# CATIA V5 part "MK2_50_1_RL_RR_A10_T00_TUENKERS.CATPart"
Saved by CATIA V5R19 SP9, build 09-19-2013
Part number: MK2_50_1_RL_RR_A10_T00_TUENKERS
Material "MISCHDICHTE": density 4834.5 kg/m3, Young's modulus 2e+11 Pa, Poisson ratio 0.266
Bounding box of the stored display mesh (mm): x -173.5 to 150.266, y -96.5 to 43, z -119.161 to 119.161
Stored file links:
  G:\Konstruktion\Modelle\Catia_V5\MK2_50_1_RL_RR_A10_T00_TUENKERS.CATPart
  G:\Konstruktion\Modelle\Catia_V5\Spannarme\SPANNARM_KPL_50_A10_216884_TUENKERS.CATPart
  C:\Catia\Tuenkers_B19SP9HF86_64\win_b64\reffiles\standard\MetricThickPitch.txt
  G:\Konstruktion\Modelle\Catia_V5\MK2_50_1_A40_T00_TUENKERS.CATPart
  G:\Konstruktion\Modelle\Catia_V5\V2_50_1_BR3_ZL_ZR_RL_RR_A40_T12_TUENKERS.CATPart
  HANDHEBEL_KPL_50_63_TUENKERS.CATPart
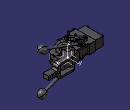
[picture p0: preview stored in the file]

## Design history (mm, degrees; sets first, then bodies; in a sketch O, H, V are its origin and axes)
AxisSystem1: origin (0, 0, 0), X (1, 0, 0), Y (0, 1, 0), Z (0, 0, 1)
Body1 (main body)
  Body2 "*DIT1\\*DIT8\\PartBody ( *SOL6 - wsp HANDHEBEL -  )"
    Solid1 "Solid.1": solid without history
  Assemble1: tool Body2
  Body3 "*DIT1\\*DIT9\\Body.9 ( *SOL4 - wsp T 12 ABFRAGE -  )"
    Sketch1 on face of Solid6, origin (0, 0, 88.5), H (1, 0, 0), V (0, 1, 0)
      line L1 (-98, 23.5) -> (-93.5, 23.5)
      line L2 (-93.5, 23.5) -> (-93.5, -23.5)
      line L3 (-93.5, -23.5) -> (-98, -23.5)
      line L4 (-98, -23.5) -> (-98, 23.5)
      line L5 (-126.5, 11.5) -> (-116.2, 11.5)
      line L6 (-116.2, 11.5) -> (-116.2, -5.5)
      line L7 (-116.2, -5.5) -> (-126.5, -5.5)
      line L8 (-126.5, -5.5) -> (-126.5, 11.5)
      reference projected line E1 (-126.5, -23.5) -> (-93.5, -23.5) from edge [face of Solid6 | face of Solid6]
      reference projected line E2 (-126.5, 23.5) -> (-93.5, 23.5) from edge [face of Solid6 | face of Solid6]
      reference projected line E3 (-93.5, 23.5) -> (-93.5, -23.5) from edge [face of Solid6 | face of Solid6]
      reference projected line E4 (-126.5, 23.5) -> (-93.5, 23.5) from edge [face of Solid6 | face of Solid6]
      reference projected line E5 (-126.5, 23.5) -> (-126.5, -23.5) from edge [face of Solid6 | face of Solid6]
      distance E1 L3 = 0
      distance L1 E2 = 0
      distance L2 L4 = 4.5
      distance L2 E3 = 0
      length L8 = 17
      distance L5 E4 = 12
      distance L6 L4 = 18.2
      distance L8 E5 = 0
      horizontal: L1 H, L3 H, L5 H, L7 H
      vertical: L2 V, L4 V, L6 V, L8 V
    Pad1: profile Sketch1, direction (0, 0, 1), length 8
    Chamfer1: length 4, angle 30, on edge [face of Pad1 from Sketch1.L2 | end face of Pad1]
    Chamfer2: length 8, angle 45, on edge [face of Pad1 from Sketch1.L8 | end face of Pad1]
  Assemble2: tool Body3
  Body4 "*DIT1\\*DIT10\\*DIT17\\PartBody ( *SOL17 - wsp DREHBOLZEN -  )"
    Solid2 "Solid.1": solid without history
  Assemble3: tool Body4
  Body5 "*DIT1\\*DIT10\\*DIT18\\PartBody ( *SOL18 - wsp STOESSEL -  )"
    Solid3 "Solid.1": solid without history
  Assemble4: tool Body5
  Body6 "*DIT1\\*DIT10\\MK_MK2_50_1_A10_A11_A12_T12_081112_3D_xSET3_1.1\\PartBody ( *SOL13 - wsp GEHAEUSE -  )"
    Solid4 "Solid.1": solid without history
  Assemble5: tool Body6
  Body7 "*DIT1\\MK_MK2_50_1_A10_A11_A12_T12_081112_3D_xSET2.1\\PartBody ( *SOL1 - wsp MK_MK2 50_1 -  -Non Smart-  )"
    Solid5 "Solid.1": solid without history
  Assemble6: tool Body7
  Body8 "*DIT1\\MK_MK2_50_1_A10_A11_A12_T12_081112_3D_xSET2.1\\Body.2 ( *SOL2 - wsp MK_MK2 50_1 -  -Non Smart-  )"
    Solid6 "Solid.1": solid without history
  Assemble7: tool Body8
  Body9 "*DIT1\\MK_MK2_50_1_A10_A11_A12_T12_081112_3D_xSET2.1\\Body.3 ( *SOL24 - wsp MK_MK2 50_1 -  )"
    Solid7 "Solid.1": solid without history
  Assemble8: tool Body9
  Body10 "*DIT1\\MK_MK2_50_1_A10_A11_A12_T12_081112_3D_xSET2.1\\Body.4 ( *SOL25 - wsp MK_MK2 50_1 -  )"
    Solid8 "Solid.1": solid without history
  Assemble9: tool Body10
  Body11 "*DIT1\\MK_MK2_50_1_A10_A11_A12_T12_081112_3D_xSET2.1\\Body.5 ( *SOL26 - wsp MK_MK2 50_1 -  )"
    Solid9 "Solid.1": solid without history
  Assemble10: tool Body11
  Body12 "*DIT1\\MK_MK2_50_1_A10_A11_A12_T12_081112_3D_xSET2.1\\Body.6 ( *SOL27 - wsp MK_MK2 50_1 -  )"
    Solid10 "Solid.1": solid without history
  Assemble11: tool Body12
  Body13 "*DIT1\\MK_MK2_50_1_A10_A11_A12_T12_081112_3D_xSET2.1\\Body.7 ( *SOL28 - wsp MK_MK2 50_1 -  )"
    Solid11 "Solid.1": solid without history
  Assemble12: tool Body13
  Rotate1: Axis edge [XY plane of AxisSystem1 | ZX plane of AxisSystem1], Angle 90, ToTransfor Assemble12
Body14 "Spannarm_kpl_50_A10_216884_Tuenkers", material "Steel"
  Sketch2 on xy-plane, origin (0, 0, 0), H (1, 0, 0), V (0, 1, 0)
    line L1 (43, 144) -> (15, 144)
    line L2 (35.6421, 1.701) -> (16.9706, -16.9706)
    line L3 (9.5, 9.5) -> (9.5, -9.5)
    line L4 (9.5, 9.5) -> (-9.5, 9.5)
    line L5 (-16.9706, 16.9706) -> (-9.5, 9.5)
    line L6 (10.6421, 44.5833) -> (-16.9706, 16.9706)
    line L7 (16.5, 58.7254) -> (16.5, 78.5)
    line L8 (43, 144) -> (43, 80)
    line L9 (9.5, -9.5) -> (16.9706, -16.9706)
    point P8 (43, 9.0589)
    point P9 (16.5, 51.7188)
    reference intersected line E1 through (0, 0) direction (-1, 0)
    reference intersected line E2 through (0, 0) direction (0, 1)
    reference intersected line E3 through (0, 0) direction (-0.7071, -0.7071)
    line L10 (41.5, 78.5) -> (41.5, 15.8431)
    reference intersected line E4 through (0, 0) direction (0, 1) from yz-plane
    line L11 (15, 80) -> (15, 144)
    point P10 (15, 80)
    reference intersected line E5 through (0, 0) direction (0, 1) from yz-plane
    arc A1 centre (43, 78.5) radius 1.5 from (41.5, 78.5) to (43, 80) cw
    arc A2 centre (15, 78.5) radius 1.5 from (16.5, 78.5) to (15, 80) ccw
    arc A3 centre (21.5, 15.8431) radius 20 from (35.6421, 1.701) to (41.5, 15.8431) ccw
    arc A4 centre (-3.5, 58.7254) radius 20 from (10.6421, 44.5833) to (16.5, 58.7254) ccw
    length L3 = 19
    length L4 = 19
    angle L5 L4 = 45
    angle L3 L9 = 45
    distance L2 L6 = 48
    distance L4 L1 = 134.5
    distance P9 L4 = 42.2188
    distance L4 E1 = 9.5
    distance L3 E2 = 9.5
    distance L2 E3 = 24
    distance L10 E4 = 41.5
    distance E5 L11 = 15
    distance L7 L10 = 25
    distance L8 L11 = 28
    length L8 = 64
    radius A3 = 20
    radius A4 = 20
    radius A1 = 1.5
    radius A2 = 1.5
    length L11 = 64
    vertical: L3 V
    horizontal: L4 H
    tangency: A3 L10, L2 A3, L7 A2, L10 A1, L7 A4, L6 A4
  Pad2: profile Sketch2, direction (0, 0, 1), length 34, mirrored extent
  Chamfer3: length 0.1, angle 45, on edge [start face of Pad2 | face of Pad2 from Sketch2.L3]; edge [start face of Pad2 | face of Pad2 from Sketch2.L4]; edge [face of Pad2 from Sketch2.L4 | end face of Pad2]; edge [face of Pad2 from Sketch2.L3 | end face of Pad2]
  Sketch3 on face of Pad2 from Sketch2.L8, origin (43, 0, 0), H (0, 1, 0), V (0, 0, 1)
    line L1 (144, -10) -> (144, 10)
    line L2 (103, 10) -> (144, 10)
    arc A1 centre (103, 18) radius 8 from (103, 10) to (95, 18) cw
    line L3 (95, 18) -> (95, 21.0383)
    line L4 (-18, 34) -> (75, 34)
    line L5 (-18, 34) -> (-18, 25)
    line L6 (74, 25) -> (-18, 25)
    arc A2 centre (74, 19) radius 6 from (74, 25) to (80, 19) cw
    line L7 (80, 19) -> (80, -19)
    arc A3 centre (74, -19) radius 6 from (80, -19) to (74, -25) cw
    line L8 (-18, -25) -> (74, -25)
    line L9 (-18, -25) -> (-18, -34)
    line L10 (75, -34) -> (-18, -34)
    line L11 (95, -21.0383) -> (95, -18)
    arc A4 centre (103, -18) radius 8 from (95, -18) to (103, -10) cw
    line L12 (103, -10) -> (144, -10)
    reference intersected line E1 through (0, 0) direction (-1, 0) from xy-plane
    reference intersected line E2 through (0, 0) direction (0, 1) from zx-plane
    reference intersected line E3 through (0, 0) direction (0, 1) from zx-plane
    reference intersected line E4 through (0, 0) direction (0, 1) from zx-plane
    line L13 (-23, -39) -> (149, -39)
    line L14 (149, -39) -> (149, 39)
    line L15 (149, 39) -> (-23, 39)
    line L16 (-23, 39) -> (-23, -39)
    reference intersected line E5 through (0, 0) direction (-1, 0) from xy-plane
    reference intersected line E6 through (0, 0) direction (0, 1) from zx-plane
    line L17 (75.5176, -33.9319) -> (87.5882, -30.6976)
    point P18 (95, -24)
    arc A5 centre (85, -21.0383) radius 10 from (95, -21.0383) to (87.5882, -30.6976) cw
    arc A6 centre (75, -32) radius 2 from (75, -34) to (75.5176, -33.9319) ccw
    point P23 (75, -34)
    line L18 (87.5882, 30.6976) -> (75.5176, 33.9319)
    arc A7 centre (75, 32) radius 2 from (75, 34) to (75.5176, 33.9319) cw
    point P26 (75, 34)
    arc A8 centre (85, 21.0383) radius 10 from (87.5882, 30.6976) to (95, 21.0383) cw
    distance L12 E1 = 10
    distance L12 L2 = 20
    distance L4 L10 = 68
    distance L6 L8 = 50
    distance L10 L12 = 24
    distance L8 L10 = 9
    radius A2 = 6
    radius A3 = 6
    radius A1 = 8
    radius A4 = 8
    distance L7 E2 = 80
    distance L3 E3 = 95
    distance L1 L5 = 162
    distance E4 L1 = 144
    distance L16 L14 = 172
    distance L15 L13 = 78
    distance L13 E5 = 39
    distance L14 E6 = 149
    radius A5 = 10
    angle L10 L17 = 15
    radius A6 = 2
    distance L11 P23 = 20
    angle L4 L18 = 15
    distance P26 L3 = 20
    radius A8 = 10
    radius A7 = 2
    tangency: L6 A2, A2 L7, L7 A3, A3 L8, L3 A1, A1 L2, A4 L12, A4 L11, A5 L11, A5 L17, A6 L10, A6 L17, A7 L4, A7 L18, A8 L18, A8 L3
    vertical: L1 V, L14 V, L16 V
    horizontal: L12 H, L13 H, L15 H
    coincidence: L5 L9, L11 L3, L11 P18
  Pocket1: profile Sketch3, direction (-1, 0, 0), length 91
  Sketch4 on face of Pad2 from Sketch2.L8, origin (43, 131.0889, -0.3784), H (0, 1, 0), V (0, 0, 1)
    point P1 (3.9111, 0.3784)
    reference intersected line E1 through (0, 0.3784) direction (-1, 0) from xy-plane
    reference intersected line E2 through (-131.0889, 0) direction (0, 1) from zx-plane
    distance P1 E2 = 135
    coincidence: P1 E1
  Hole1: placed by Sketch4, at (43, 135, 0) direction (-1, 0, 0), diameter 6, through (limit type 6)
  Sketch5 on face of Pad2 from Sketch2.L8, origin (43, 113.9529, 0.5693), H (0, 1, 0), V (0, 0, 1)
    point P1 (-8.9529, -0.5693)
    reference projected point E1 (21.0471, -0.5693) from axis of face of Hole1
    reference intersected line E2 through (0, -0.5693) direction (-1, 0) from xy-plane
    distance P1 E1 = 30
    coincidence: P1 E2
  Hole2: placed by Sketch5, at (43, 105, 0) direction (-1, 0, 0), diameter 6, through (limit type 6)
  Sketch6 on face of Pad2 from Sketch2.L8, origin (43, 123.4122, -0.1089), H (0, 1, 0), V (0, 0, 1)
    point P1 (-3.4122, 0.1089)
    reference projected point E1 (11.5878, 0.1089) from axis of face of Hole1
    reference projected point E2 (-18.4122, 0.1089) from axis of face of Hole2
    distance P1 E1 = 15
    distance E2 P1 = 15
  Hole3: placed by Sketch6, at (43, 120, 0) direction (-1, 0, 0), diameter 9, through (limit type 6)
  Sketch7 on face of Pad2 from Sketch2.L8, origin (43, 93.5248, 1.4062), H (0, 1, 0), V (0, 0, 1)
    point P1 (-3.5248, -1.4062)
    reference projected point E1 (26.4752, -1.4062) from axis of face of Hole3
    reference projected point E2 (11.4752, -1.4062) from axis of face of Hole2
    distance P1 E1 = 30
    distance P1 E2 = 15
  Hole4: placed by Sketch7, at (43, 90, 0) direction (-1, 0, 0), diameter 9, through (limit type 6)
  Sketch8 on face of Pad2 from Sketch2.L9, origin (13.7879, -13.7879, 28.7565), H (0.7071, -0.7071, 0), V (0, 0, 1)
    point P1 (-1.4991, 0.2435)
    reference intersected line E1 through (0, -28.7565) direction (-1, 0) from xy-plane
    reference projected line E2 (-19.4991, -62.7565) -> (-19.4991, 5.2435) from edge [face of Pad2 from Sketch2.L3 | face of Pad2 from Sketch2.L4]
    distance P1 E1 = 29
    distance E2 P1 = 18
  Hole5: placed by Sketch8, at (12.7279, -12.7279, 29) direction (0.7071, 0.7071, 0), diameter 4.917, depth 16, V-bottom angle 120, threaded "M6", thread diameter 6, thread depth 14, pitch 1
  RectPattern1: of Hole5, direction 1 instances 2, spacing 58, along edge [face of Pad2 from Sketch2.L3 | face of Pad2 from Sketch2.L4] reversed, direction 2 instances 2, spacing 36, along edge [face of Pad2 from Sketch2.L9 | face of Pocket1] reversed
  Body15 "KLEMMFLANSCH KPL"
    Sketch9 on xy-plane, origin (0, 0, 0), H (1, 0, 0), V (0, 1, 0)
      line L1 (-18.3848, 15.5563) -> (-26.8771, 7.064)
      line L2 (-26.8771, 7.064) -> (-18.7454, -1.0677)
      line L3 (-18.7454, -1.0677) -> (-23.6951, -6.0175)
      line L4 (-23.6951, -6.0175) -> (-6.0175, -23.6951)
      line L5 (-6.0175, -23.6951) -> (-1.0677, -18.7454)
      line L6 (-1.0677, -18.7454) -> (7.064, -26.8771)
      line L7 (7.064, -26.8771) -> (16.9635, -16.9776)
      line L8 (16.9635, -16.9776) -> (9.3267, -9.3409)
      line L9 (9.3267, -9.3409) -> (-9.3409, -9.3409)
      point P10 (-9.3409, -9.3409)
      line L10 (-9.3409, -9.3409) -> (-9.3409, 6.5125)
      line L11 (-9.3409, 6.5125) -> (-18.3848, 15.5563)
      reference intersected line E1 through (0, 0) direction (-0.7071, -0.7071)
      reference intersected line E2 through (0, 0) direction (-0.7071, 0.7071)
      distance L4 L8 = 21
      angle L5 L6 = 90
      angle L9 L8 = 45
      distance L7 L5 = 11.5
      distance L5 L3 = 25
      distance L7 L1 = 48
      distance P10 L8 = 13.2
      distance P10 L5 = 12.5
      distance L4 L6 = 7
      angle L9 L10 = 90
      distance E2 L11 = 2
      distance L11 L8 = 1.99
      coincidence: L2 L6, E1 P10
    Pad3: profile Sketch9, direction (0, 0, 1), length 34, opposite side length -24
    Sketch10 on face of Pad3 from Sketch9.L6, origin (-9.9066, -9.9066, 0), H (0.7071, -0.7071, 0), V (0, 0, 1)
      circle A1 centre (18, 29) radius 5
      point P1 (18, 29)
      point P2 (18, 29)
      reference projected line E1 (12.5, 34) -> (24, 34) from edge [face of Pad3 from Sketch9.L6 | end face of Pad3]
      reference projected line E2 (24, 24) -> (24, 34) from edge [face of Pad3 from Sketch9.L7 | face of Pad3 from Sketch9.L6]
      radius A1 = 5
      distance E1 P2 = 5
      distance P2 E2 = 6
      coincidence: P2 P1
    Pad4: profile Sketch10, direction (-0.7071, -0.7071, 0), length 1.2
    RectPattern2: of Pad4, direction 1 instances 2, spacing 36, along edge [start face of Pad3 | face of Pad3 from Sketch9.L4] reversed
    Chamfer4: length 0.1, angle 45, on edge [face of Pad4 from Sketch10.A1 | end face of Pad4]; edge [face of RectPattern2 | face of RectPattern2]
    Sketch11 on face of Pad3 from Sketch9.L6, origin (-9.9066, -9.9066, 0), H (0.7071, -0.7071, 0), V (0, 0, 1)
      circle A1 centre (18, 29) radius 3
      point P1 (18, 29)
      reference projected line E1 (12.5, 24) -> (24, 24) from edge [start face of Pad3 | face of Pad3 from Sketch9.L6]
      reference projected line E2 (24, 24) -> (24, 34) from edge [face of Pad3 from Sketch9.L7 | face of Pad3 from Sketch9.L6]
      radius A1 = 3
      distance P1 E1 = 5
      distance E2 P1 = 6
    Pad5: profile Sketch11, direction (0.7071, 0.7071, 0), length 20
    RectPattern3: of Pad5, direction 1 instances 2, spacing 36, along edge [start face of Pad3 | face of Pad3 from Sketch9.L4] reversed
    Sketch12 on end face of Pad4, origin (-10.7551, -10.7551, 0), H (0.7071, -0.7071, 0), V (0, 0, 1)
      circle A1 centre (18, 29) radius 5
      point P1 (18, 29)
      circle A2 centre (-18, 29) radius 5
      point P2 (-18, 29)
      reference projected line E1 (-24, 24) -> (-12.5, 24) from edge [start face of Pad3 | face of Pad3 from Sketch9.L2]
      reference projected line E2 (12.5, 24) -> (24, 24) from edge [start face of Pad3 | face of Pad3 from Sketch9.L6]
      reference projected line E3 (24, 24) -> (24, 34) from edge [face of Pad3 from Sketch9.L7 | face of Pad3 from Sketch9.L6]
      reference projected line E4 (-24, 24) -> (-24, 34) from edge [face of Pad3 from Sketch9.L2 | face of Pad3 from Sketch9.L1]
      radius A1 = 5
      radius A2 = 5
      distance E1 P2 = 5
      distance E2 P1 = 5
      distance E3 P1 = 6
      distance E4 P2 = 6
    Pad6: profile Sketch12, direction (-0.7071, -0.7071, 0), length 6
    Fillet1: radius 0.5, on edge [face of Pad6 from Sketch12.A1 | end face of Pad6]; edge [face of Pad6 from Sketch12.A2 | end face of Pad6]
    Chamfer5: length 0.1, angle 45, on edge [face of Pad3 from Sketch9.L9 | end face of Pad3]; edge [face of Pad3 from Sketch9.L10 | end face of Pad3]
    Mirror1: of the body so far, about xy-plane
  Assemble13: tool Body15
  Sketch13 on face of Pocket1 from Sketch3.L6, origin (0, 0, 25), H (1, 0, 0), V (0, -1, 0)
    line L1 (16.9706, 16.9706) -> (9.5, 9.5)
    line L2 (9.5, 9.5) -> (9.5, -9.5)
    point P3 (9.5, -9.5)
    line L3 (9.5, -9.5) -> (-9.5, -9.5)
    line L4 (-9.5, -9.5) -> (-16.9706, -16.9706)
    line L5 (-16.9706, -16.9706) -> (0.7071, -34.6482)
    line L6 (0.7071, -34.6482) -> (34.6482, -0.7071)
    line L7 (34.6482, -0.7071) -> (16.9706, 16.9706)
    reference intersected line E1 through (0, 0) direction (0.7071, 0.7071)
    reference intersected line E2 through (0, 0) direction (0.7071, -0.7071)
    reference intersected line E3 through (0, 0) direction (0.7071, -0.7071)
    distance L1 L6 = 25
    angle L2 L3 = 90
    length L2 = 19
    length L3 = 19
    distance L7 L5 = 48
    distance L7 E3 = 24
    coincidence: E1 L1, L1 L4, E2 P3
  Pad7: profile Sketch13, direction (0, 0, -1), length 1
  Mirror2: of Pad7, Sketch13, about xy-plane
  Rotate2: Axis edge [XY plane of AxisSystem1 | ZX plane of AxisSystem1], Angle 180, ToTransfor Mirror2
  Rotate3: Axis edge [ZX plane of AxisSystem1 | YZ plane of AxisSystem1], Angle 90, ToTransfor Rotate2
Body16 "ENDLAGENRASTE_LINKS"
  Body17 "LUMP108"
    Solid12 "Manifold Solid #2147": solid without history
  Assemble14: tool Body17
  Body18 "LUMP109"
    Solid13 "Manifold Solid #2556": solid without history
  Assemble15: tool Body18
  Body19 "LUMP110"
    Solid14 "Manifold Solid #2941": solid without history
  Assemble16: tool Body19
  Body20 "LUMP111"
    Solid15 "Manifold Solid #3571": solid without history
  Assemble17: tool Body20
  Body21 "LUMP112"
    Solid16 "Manifold Solid #4879": solid without history
  Assemble18: tool Body21
  Body22 "LUMP114"
    Solid17 "Manifold Solid #6444": solid without history
  Assemble19: tool Body22
  Body23 "LUMP117"
    Solid18 "Manifold Solid #8121": solid without history
  Assemble20: tool Body23
  Body24 "LUMP118"
    Solid19 "Manifold Solid #9264": solid without history
  Assemble21: tool Body24
  Body25 "LUMP120"
    Solid20 "Manifold Solid #10792": solid without history
  Assemble22: tool Body25
  Body26 "LUMP122"
    Solid21 "Manifold Solid #11586": solid without history
  Assemble23: tool Body26
  Body27 "LUMP126"
    Solid22 "Manifold Solid #12918": solid without history
  Assemble24: tool Body27
  Body28 "LUMP127"
    Solid23 "Manifold Solid #13327": solid without history
  Assemble25: tool Body28
  Body29 "LUMP130"
    Solid24 "Manifold Solid #14250": solid without history
  Assemble26: tool Body29
  Body30 "LUMP132"
    Solid25 "Manifold Solid #15068": solid without history
  Assemble27: tool Body30
  Body31 "LUMP133"
    Solid26 "Manifold Solid #15325": solid without history
  Assemble28: tool Body31
  Body32 "LUMP134"
    Solid27 "Manifold Solid #15582": solid without history
  Assemble29: tool Body32
  Body33 "LUMP135"
    Solid28 "Manifold Solid #15839": solid without history
  Assemble30: tool Body33
  Body34 "LUMP124"
    Solid29 "Manifold Solid #12404": solid without history
  Assemble31: tool Body34
  Rotate4: Axis edge, Angle 90, ToTransfor Assemble31
Body35 "ENDLAGENRASTE_RECHTS"
  Solid30 "Manifold Solid #290": solid without history
  Body36 "LUMP105"
    Solid31 "Manifold Solid #920": solid without history
  Assemble32: tool Body36
  Body37 "LUMP106"
    Solid32 "Manifold Solid #1329": solid without history
  Assemble33: tool Body37
  Body38 "LUMP107"
    Solid33 "Manifold Solid #1738": solid without history
  Assemble34: tool Body38
  Body39 "LUMP113"
    Solid34 "Manifold Solid #6187": solid without history
  Assemble35: tool Body39
  Body40 "LUMP115"
    Solid35 "Manifold Solid #6701": solid without history
  Assemble36: tool Body40
  Body41 "LUMP116"
    Solid36 "Manifold Solid #7411": solid without history
  Assemble37: tool Body41
  Body42 "LUMP119"
    Solid37 "Manifold Solid #10407": solid without history
  Assemble38: tool Body42
  Body43 "LUMP121"
    Solid38 "Manifold Solid #11177": solid without history
  Assemble39: tool Body43
  Body44 "LUMP123"
    Solid39 "Manifold Solid #11995": solid without history
  Assemble40: tool Body44
  Body45 "LUMP124"
    Solid40 "Manifold Solid #12404": solid without history
    Symmetry1: Reference ZX plane of AxisSystem1, ToTransfor Solid40
  Assemble41: tool Body45
  Body46 "LUMP125"
    Solid41 "Manifold Solid #12661": solid without history
  Assemble42: tool Body46
  Body47 "LUMP128"
    Solid42 "Manifold Solid #13736": solid without history
  Assemble43: tool Body47
  Body48 "LUMP129"
    Solid43 "Manifold Solid #13993": solid without history
  Assemble44: tool Body48
  Body49 "LUMP131"
    Solid44 "Manifold Solid #14659": solid without history
  Assemble45: tool Body49
  Body50 "LUMP136"
    Solid45 "Manifold Solid #16096": solid without history
  Assemble46: tool Body50
  Rotate5: Axis edge, Angle 90, ToTransfor Assemble46
Body51 "Handhebel_KPL_218625_TUENKERS.1"
  Solid46: solid without history
  Body52 "Handhebel_KPL_218625_TUENKERS.2"
    Solid47: solid without history
  Assemble47: tool Body52
  Translate1: Direction edge [ZX plane of AxisSystem1 | YZ plane of AxisSystem1], ToTransfor Assemble47, Length 25
  Translate2: Direction edge [XY plane of AxisSystem1 | ZX plane of AxisSystem1], ToTransfor Translate1, Length -68
  Translate3: Direction edge [YZ plane of AxisSystem1 | XY plane of AxisSystem1], ToTransfor Translate2, Length -4
Body53 "Handhebel_KPL_218625_TUENKERS.1"
  Solid48: solid without history
  Body54 "Handhebel_KPL_218625_TUENKERS.2"
    Solid49: solid without history
  Assemble48: tool Body54
  Translate4: Direction edge [ZX plane of AxisSystem1 | YZ plane of AxisSystem1], Length 25, ToTransfor Assemble48
  Translate5: Direction edge [XY plane of AxisSystem1 | ZX plane of AxisSystem1], Length -68, ToTransfor Translate4
  Translate6: Direction edge [YZ plane of AxisSystem1 | XY plane of AxisSystem1], Length -4, ToTransfor Translate5
  Symmetry2: ToTransfor Translate6, Reference XY plane of AxisSystem1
